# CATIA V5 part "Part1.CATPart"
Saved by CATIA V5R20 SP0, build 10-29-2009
Part number: Part1
Bounding box of the stored display mesh (mm): x -119.993 to 119.993, y -119.993 to 119.993, z 0 to 560
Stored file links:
  E:\Ehsan\Catia\Tamrin\Digital Mockup\1\Part1.CATPart
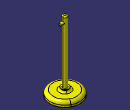
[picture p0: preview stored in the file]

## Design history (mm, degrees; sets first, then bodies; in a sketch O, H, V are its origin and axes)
Body1 (main body)
  Sketch1 on yz-plane, origin (0, 0, 0), H (0, 1, 0), V (0, 0, 1)
    point P1 (0, 60)
    line L1 (0, 60) -> (30, 60)
    line L2 (30, 60) -> (30, 40)
    line L3 (30, 40) -> (120, 40)
    line L4 (120, 40) -> (120, 0)
    point P5 (120, 0)
    line L5 (120, 0) -> (0, 0)
    line L6 (0, 0) -> (0, 60)
    distance P1 H = 60
    length L1 = 30
    length L2 = 20
    length L3 = 90
    coincidence: P1 V, P5 H
    horizontal: L1 H, L3 H, L5 H
    vertical: L2 V, L4 V, L6 V
  Shaft1: profile Sketch1, axis Sketch1.L6, angle 360
  Sketch2 on face of Shaft1 from Sketch1.L1, origin (0, 0, 60), H (1, 0, 0), V (0, 1, 0)
    circle A1 centre (0, 0) radius 17.5
    reference projected circle E1 centre (0, 0) radius 30 from edge [face of Shaft1 from Sketch1.L1 | face of Shaft1 from Sketch1.L2]
    concentricity: A1 E1
  Pad1: profile Sketch2, direction (0, 0, 1), length 500
  Fillet1: radius 15, on edge [face of Shaft1 from Sketch1.L2 | face of Shaft1 from Sketch1.L3]
  Fillet2: radius 25, on edge [face of Shaft1 from Sketch1.L3 | face of Shaft1 from Sketch1.L4]
  Sketch3 on yz-plane, origin (0, 0, 0), H (0, 1, 0), V (0, 0, 1)
    circle A1 centre (0, 510) radius 10
    point P1 (0, 510)
    reference projected line E1 (-17.5, 560) -> (17.5, 560) from edge [face of Pad1 from Sketch2.A1 | end face of Pad1]
    radius A1 = 10
    distance A1 E1 = 40
    coincidence: P1 V
  Pad2: profile Sketch3, direction (1, 0, 0), length 40
  Fillet3: radius 10, on end face of Pad1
